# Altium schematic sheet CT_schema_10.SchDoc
size 281 x 153 mm
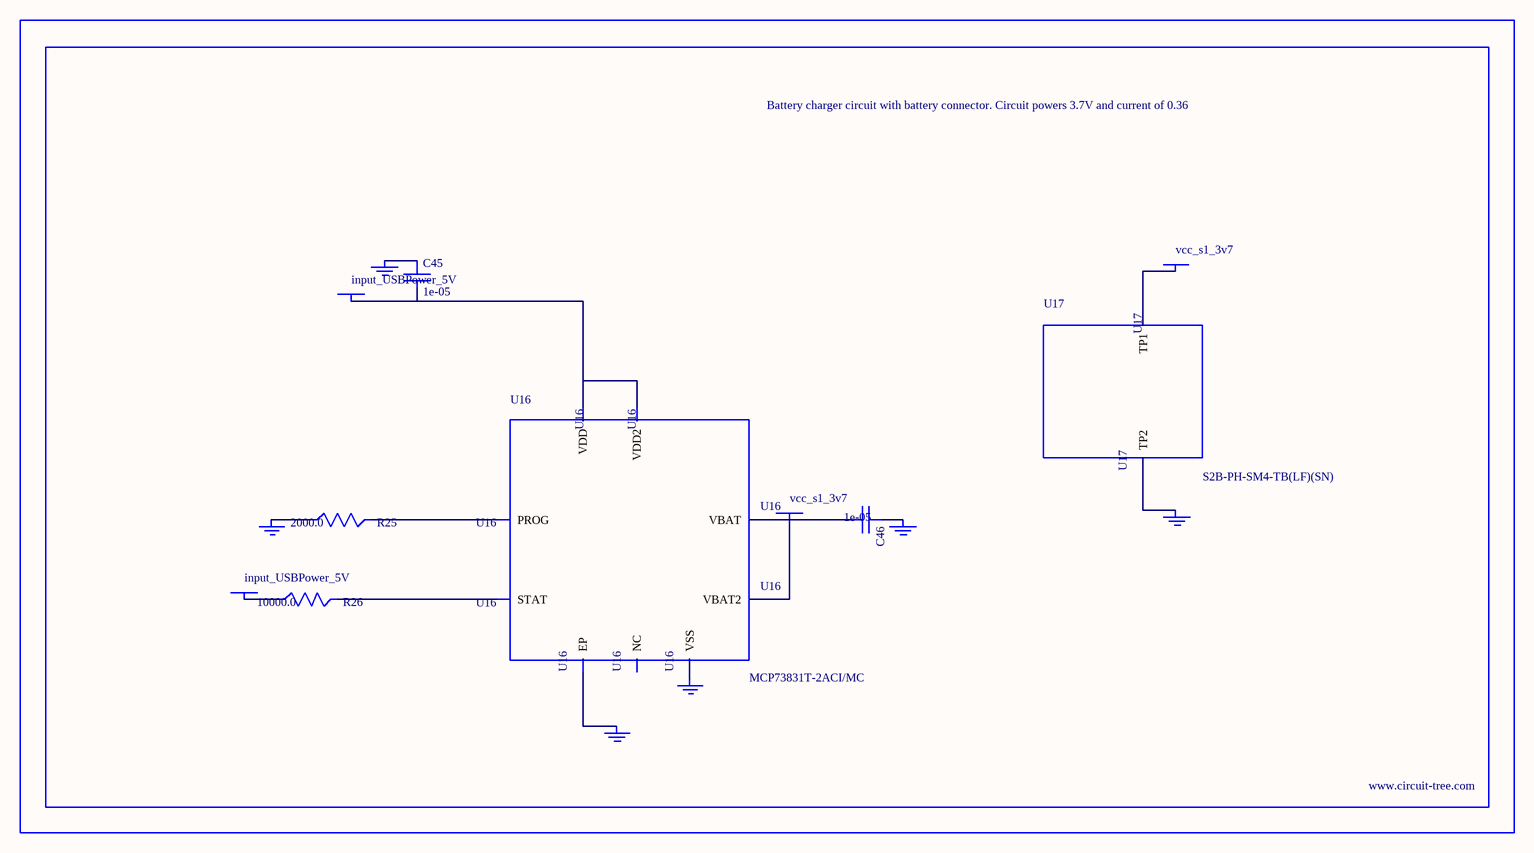
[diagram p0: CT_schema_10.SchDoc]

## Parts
BORDER9  (no value)
C45  1e-05  [C1206]
C46  1e-05  [C1206]
GND_INSTANCE_9_0  (no value)
GND_INSTANCE_9_1  (no value)
GND_INSTANCE_9_2  (no value)
GND_INSTANCE_9_3  (no value)
GND_INSTANCE_9_4  (no value)
GND_INSTANCE_9_5  (no value)
POWER_INSTANCE_9_0  input_USBPower_5V
POWER_INSTANCE_9_1  input_USBPower_5V
POWER_INSTANCE_9_2  vcc_s1_3v7
POWER_INSTANCE_9_3  vcc_s1_3v7
R25  2000.0  [R0603]
R26  10000.0  [R0603]
U16  MCP73831T-2ACI/MC  [DFN8_2X3MC]
U17  S2B-PH-SM4-TB(LF)(SN)  [JST-2-SMD]

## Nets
NetC45_1: C45.1 GND_INSTANCE_9_0.0(GND)
NetC45_2: C45.2 POWER_INSTANCE_9_0.0(PWR) U16.1(VDD) U16.2(VDD2)
NetC46_1: C46.1 GND_INSTANCE_9_1.0(GND)
NetC46_2: C46.2 POWER_INSTANCE_9_2.0(PWR) U16.3(VBAT) U16.4(VBAT2)
NetGND_INSTANCE_9_2_0: GND_INSTANCE_9_2.0(GND) R25.1
NetGND_INSTANCE_9_3_0: GND_INSTANCE_9_3.0(GND) U16.9(EP)
NetGND_INSTANCE_9_4_0: GND_INSTANCE_9_4.0(GND) U16.6(VSS)
NetGND_INSTANCE_9_5_0: GND_INSTANCE_9_5.0(GND) U17.2(TP2)
NetPOWER_INSTANCE_9_1_0: POWER_INSTANCE_9_1.0(PWR) R26.1
NetPOWER_INSTANCE_9_3_0: POWER_INSTANCE_9_3.0(PWR) U17.1(TP1)
NetR25_2: R25.2 U16.8(PROG)
NetR26_2: R26.2 U16.5(STAT)

Not connected (* = marked no-connect by the designer): U16 7(NC)

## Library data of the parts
BORDER9 = BORDER_PAGE9
C45 C46 = C1206C106K3RACTU
GND_INSTANCE_9_0-GND_INSTANCE_9_5 = GND
POWER_INSTANCE_9_0-POWER_INSTANCE_9_3 = PWR
R25 = RC0603JR-072KL
R26 = RC0603JR-0710KL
